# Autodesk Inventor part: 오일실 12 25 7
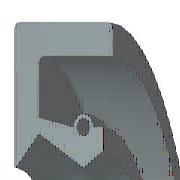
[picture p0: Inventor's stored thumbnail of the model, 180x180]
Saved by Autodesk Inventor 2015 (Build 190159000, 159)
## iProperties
IsCustomPart: 1
Created: 2012-02
Part Number: 오일실 12 25 7
Material: 고무
Description: 오일-실
Document SubType Name: Modeling
Standard: KS B 2804
Designer: test
Standards Organization: KS
Language: ko-KR
Size Designation: D - 12 25 7
Categories: <MemberInstance><Categories><Category DisplayName="샤프트 부품" InternalName="7f7aeb1f-a693-4053-b835-cee3144e0d98" Mnemonic="SHFT"><Category DisplayName="실링" Intern
Density: 0.93 g/cm^3
Appearance: 고무 - 검은색 - 버전 1.1
Author: test
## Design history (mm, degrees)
revolve "본체" stored, may be unused: angle "d17" = 90 deg
revolve "스프링1" stored, may be unused: angle "d18" = 90 deg
body "Solid1"
sketch "스케치1"
  geometry: L1 (0, 12.5)-(7, 12.5); L2 (7, 10.75)-(1.75, 10.75); L3 (1.75, 7.75)-(4.9, 6); L4 (4.9, 6)-(0, 6); L5 (0, 0)-(9.586, 0) reference; L6 (4.9, 6)-(6.3, 6.875); L7 (0, 18)-(0, -3) reference; L8 (-1.941, 0)-(11.507, 0) reference; L9 (4.2, 8.1)-(1.75, 8.59); L10 (1.75, 8.59)-(1.75, 10.75); L11 (0, 12.5)-(0, 6.088); L12 (4.9, 6)-(0, 6); L13 (1.75, 7.75)-(0.152, 6.028); L14 (7, 12.5)-(7, 10.75); L15 (5.6, 8.1)-(6.3, 8.1); L16 (6.3, 8.1)-(6.3, 6.875); C1 r 0.455 at (4.9, 8.1); A1 r 0.7 centre (4.9, 8.1) between (5.6, 8.1) and (4.2, 8.1); A2 r 0.088 centre (0.088, 6.088) between (0, 6.088) and (0.152, 6.028); 1 further point
  constraints: 28 end point, 5 horizontal alignment, 5 point on line, 4 point on circle, 4 vertical alignment, 3 centre point, 3 tangent, 2 collinear, 2 horizontal, 2 perpendicular, 1 coincident, 1 parallel
  dimensions: "d0" = 25 diameter of L1 L5 (= SD2); "d1" = 1.75 distance of L1.end L2.start (= SD); "d2" = 0.91 diameter of C1 (= SPDI); "d3" = 1.4 diameter of A1 (= SPDA); "d4" = 12 diameter of L3.end L5 (= NND); "d5" = 15.5 diameter of L3.start L5 (= TKDM); "d7" = 17.18 diameter of L9.end L5 (= TKDM + 0.24 x SWDT); "d8" = 1.75 distance between parallel lines of L11 L10 (= SD); "d9" = 4.9 distance from line of L11 C1.centre (= SPDST); "d10" = 16.2 diameter of C1.centre L5 (= HLDM); "d11" = 0.0875 radius of A2 (= 0.25 x LAB); "d12" = 6.3 distance between parallel lines of L11 L16 (= SDI); "d13" = 13.75 diameter of L6.end L5 (= ABDM); "d14" = 7 distance from line of L11 L1.end (= SWDT)
fillet "모깎기1" dims "d6" = 0.3 (= RR)
other parameters: "SD2" = 25 [user parameter; used in 1 equation term], "SWDT" = 7 [user parameter; used in 2 equation terms], "RR" = 0.3 [user parameter; used in 1 equation term], "SD" = 1.75 [user parameter; used in 2 equation terms], "NND" = 12 [user parameter; used in 1 equation term], "SPDA" = 1.4 [user parameter; used in 1 equation term], "SPDI" = 0.91 [user parameter; used in 1 equation term], "TKDM" = 15.5 [user parameter; used in 2 equation terms], "HLDM" = 16.2 [user parameter; used in 1 equation term], "ABDM" = 13.75 [user parameter; used in 1 equation term], "SDI" = 6.3 [user parameter; used in 1 equation term], "SPDST" = 4.9 [user parameter; used in 1 equation term], "LAB" = 0.35 [user parameter; used in 1 equation term], "d15" = 0, "d16" = 0, "d19" = 0
